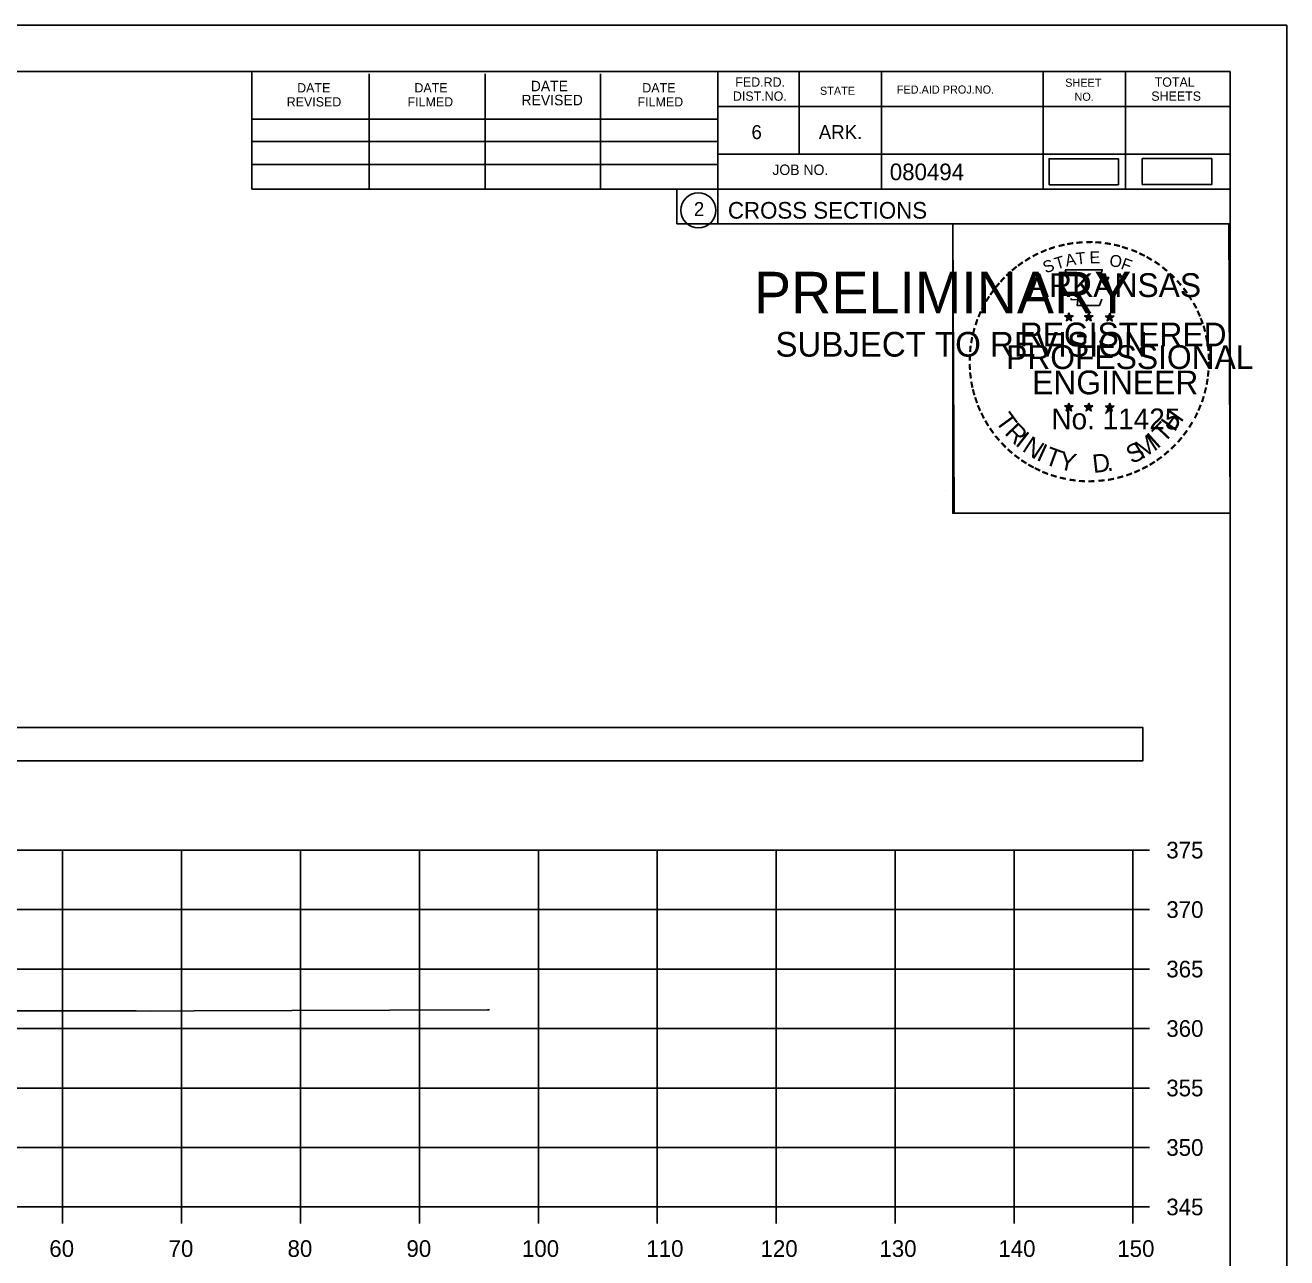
# Model space of a CAD drawing. Extents: x 1376273 to 1384221, y 378927 to 384592.
# Drawn here: x 1379448 to 1379554.1, y 381501.6 to 381605.2 of the extents above; entities that cross this region are included whole.
import ezdxf

# ---------------------------------------------------------------- set-up
doc = ezdxf.new("R2010")
doc.units = 0
for name, color, linetype in [('R_Axis', 7, 'Continuous'), ('R_Axis Annot', 7, 'Continuous'), ('R_Border', 7, 'Continuous'), ('R_Border PE', 7, 'Continuous'), ('R_Border Prem', 7, 'Continuous'), ('R_Drive', 7, 'Continuous'), ('R_Exist Surface', 7, 'Continuous'), ('R_Grid', 7, 'Continuous'), ('R_No Plot', 7, 'Continuous')]:
    doc.layers.add(name, color=color, linetype=linetype)

msp = doc.modelspace()

# ---------------------------------------------------------------- linework, layer by layer
at = {"layer": 'R_Axis'}
for p, q in [((1379541.15, 381505.85), (1379541.15, 381535.85)), ((1379542.55, 381535.85), (1379541.15, 381535.85)), ((1379542.55, 381530.85), (1379541.15, 381530.85)), ((1379542.55, 381525.85), (1379541.15, 381525.85)), ((1379542.55, 381520.85), (1379541.15, 381520.85)), ((1379542.55, 381515.85), (1379541.15, 381515.85)), ((1379542.55, 381510.85), (1379541.15, 381510.85)), ((1379241.15, 381505.85), (1379541.15, 381505.85)), ((1379451.15, 381504.45), (1379451.15, 381505.85)), ((1379461.15, 381504.45), (1379461.15, 381505.85)), ((1379471.15, 381504.45), (1379471.15, 381505.85)), ((1379481.15, 381504.45), (1379481.15, 381505.85)), ((1379491.15, 381504.45), (1379491.15, 381505.85)), ((1379501.15, 381504.45), (1379501.15, 381505.85)), ((1379511.15, 381504.45), (1379511.15, 381505.85)), ((1379521.15, 381504.45), (1379521.15, 381505.85)), ((1379531.15, 381504.45), (1379531.15, 381505.85)), ((1379541.15, 381504.45), (1379541.15, 381505.85)), ((1379542.55, 381505.85), (1379541.15, 381505.85))]:
    msp.add_line(p, q, dxfattribs=at)
at = {"layer": 'R_Axis Annot'}
msp.add_lwpolyline([(1379240.17, 381543.35), (1379541.97, 381543.35), (1379541.97, 381546.17), (1379240.17, 381546.17)], close=True, dxfattribs=at)
at = {"layer": 'R_Border'}
for p, q in [((1379233.15, 381601.31), (1379549.33, 381601.31)), ((1379467.07, 381591.43), (1379467.07, 381601.31)), ((1379476.93, 381591.43), (1379476.93, 381601.11)), ((1379486.69, 381591.43), (1379486.69, 381601.11)), ((1379496.37, 381591.43), (1379496.37, 381601.11)), ((1379506.23, 381601.31), (1379506.23, 381588.51)), ((1379513.07, 381601.31), (1379513.07, 381594.37)), ((1379520.01, 381601.31), (1379520.01, 381591.43)), ((1379533.59, 381601.31), (1379533.59, 381591.43)), ((1379540.53, 381601.31), (1379540.53, 381591.43)), ((1379549.33, 381395.85), (1379549.33, 381601.31)), ((1379549.33, 381598.37), (1379506.23, 381598.37)), ((1379549.33, 381598.39), (1379549.33, 381598.39)), ((1379467.07, 381597.29), (1379506.23, 381597.29)), ((1379467.07, 381595.43), (1379506.23, 381595.43)), ((1379549.33, 381594.37), (1379506.23, 381594.37)), ((1379509.19, 381594.37), (1379549.33, 381594.37)), ((1379467.07, 381591.43), (1379467.07, 381593.49)), ((1379467.07, 381593.49), (1379506.23, 381593.49)), ((1379549.33, 381591.43), (1379467.07, 381591.43)), ((1379506.23, 381588.51), (1379549.33, 381588.51))]:
    msp.add_line(p, q, dxfattribs=at)
msp.add_circle((1379504.61, 381589.64), 1.47, dxfattribs=at)
at = {"layer": 'R_Border PE'}
for p, q in [((1379535.41, 381580.76), (1379535.76, 381580.65)), ((1379535.41, 381580.76), (1379535.67, 381580.72)), ((1379535.41, 381580.76), (1379535.65, 381580.64)), ((1379535.55, 381580.35), (1379535.76, 381580.65)), ((1379535.55, 381580.35), (1379535.67, 381580.6)), ((1379535.55, 381580.35), (1379535.76, 381580.57)), ((1379535.76, 381581.02), (1379535.72, 381580.76)), ((1379535.76, 381580.65), (1379535.76, 381581.02)), ((1379535.76, 381581.02), (1379535.81, 381580.77)), ((1379536.11, 381580.76), (1379535.76, 381580.65)), ((1379535.97, 381580.35), (1379535.76, 381580.65)), ((1379535.97, 381580.35), (1379535.76, 381580.57)), ((1379536.11, 381580.76), (1379535.82, 381580.71)), ((1379535.97, 381580.35), (1379535.84, 381580.64)), ((1379536.11, 381580.76), (1379535.9, 381580.66)), ((1379537.08, 381580.76), (1379537.43, 381580.65)), ((1379537.08, 381580.76), (1379537.34, 381580.72)), ((1379537.08, 381580.76), (1379537.32, 381580.64)), ((1379537.22, 381580.35), (1379537.43, 381580.65)), ((1379537.22, 381580.35), (1379537.34, 381580.6)), ((1379537.22, 381580.35), (1379537.43, 381580.57)), ((1379537.43, 381581.02), (1379537.39, 381580.76)), ((1379537.43, 381580.65), (1379537.43, 381581.02)), ((1379537.43, 381581.02), (1379537.48, 381580.77)), ((1379537.78, 381580.76), (1379537.43, 381580.65)), ((1379537.64, 381580.35), (1379537.43, 381580.65)), ((1379537.64, 381580.35), (1379537.43, 381580.57)), ((1379537.78, 381580.76), (1379537.49, 381580.71)), ((1379537.64, 381580.35), (1379537.51, 381580.64)), ((1379537.78, 381580.76), (1379537.57, 381580.66)), ((1379538.85, 381580.75), (1379539.2, 381580.64)), ((1379538.85, 381580.75), (1379539.1, 381580.7)), ((1379538.85, 381580.75), (1379539.08, 381580.63)), ((1379538.98, 381580.34), (1379539.2, 381580.64)), ((1379538.98, 381580.34), (1379539.11, 381580.59)), ((1379538.98, 381580.34), (1379539.19, 381580.56)), ((1379539.2, 381581), (1379539.15, 381580.75)), ((1379539.41, 381580.34), (1379539.19, 381580.56)), ((1379539.2, 381580.64), (1379539.2, 381581)), ((1379539.2, 381581), (1379539.24, 381580.75)), ((1379539.54, 381580.75), (1379539.2, 381580.64)), ((1379539.41, 381580.34), (1379539.2, 381580.64)), ((1379539.54, 381580.75), (1379539.26, 381580.7)), ((1379539.41, 381580.34), (1379539.27, 381580.63)), ((1379539.54, 381580.75), (1379539.34, 381580.65)), ((1379535.41, 381573.19), (1379535.76, 381573.08)), ((1379535.41, 381573.19), (1379535.66, 381573.14)), ((1379535.41, 381573.19), (1379535.65, 381573.07)), ((1379535.54, 381572.78), (1379535.76, 381573.08)), ((1379535.54, 381572.78), (1379535.67, 381573.02)), ((1379535.54, 381572.78), (1379535.76, 381573)), ((1379535.76, 381573.44), (1379535.72, 381573.19)), ((1379535.76, 381573.08), (1379535.76, 381573.44)), ((1379535.76, 381573.44), (1379535.81, 381573.19)), ((1379536.1, 381573.19), (1379535.76, 381573.08)), ((1379535.97, 381572.78), (1379535.76, 381573.08)), ((1379535.97, 381572.78), (1379535.76, 381572.99)), ((1379536.1, 381573.19), (1379535.82, 381573.14)), ((1379535.97, 381572.78), (1379535.83, 381573.07)), ((1379536.1, 381573.19), (1379535.9, 381573.09)), ((1379537.08, 381573.19), (1379537.43, 381573.08)), ((1379537.08, 381573.19), (1379537.33, 381573.14)), ((1379537.08, 381573.19), (1379537.31, 381573.07)), ((1379537.21, 381572.78), (1379537.43, 381573.08)), ((1379537.21, 381572.78), (1379537.34, 381573.02)), ((1379537.21, 381572.78), (1379537.42, 381573)), ((1379537.43, 381573.44), (1379537.39, 381573.19)), ((1379537.64, 381572.78), (1379537.42, 381572.99)), ((1379537.43, 381573.08), (1379537.43, 381573.44)), ((1379537.43, 381573.44), (1379537.48, 381573.19)), ((1379537.77, 381573.19), (1379537.43, 381573.08)), ((1379537.64, 381572.78), (1379537.43, 381573.08)), ((1379537.77, 381573.19), (1379537.49, 381573.14)), ((1379537.64, 381572.78), (1379537.5, 381573.07)), ((1379537.77, 381573.19), (1379537.57, 381573.09)), ((1379538.84, 381573.18), (1379539.19, 381573.07)), ((1379538.84, 381573.18), (1379539.1, 381573.13)), ((1379538.84, 381573.18), (1379539.08, 381573.06)), ((1379538.98, 381572.77), (1379539.19, 381573.07)), ((1379538.98, 381572.77), (1379539.1, 381573.01)), ((1379538.98, 381572.77), (1379539.19, 381572.99)), ((1379539.19, 381573.43), (1379539.15, 381573.18)), ((1379539.19, 381573.07), (1379539.19, 381573.43)), ((1379539.19, 381573.43), (1379539.24, 381573.18)), ((1379539.54, 381573.18), (1379539.19, 381573.07)), ((1379539.41, 381572.77), (1379539.19, 381573.07)), ((1379539.41, 381572.77), (1379539.19, 381572.98)), ((1379539.54, 381573.18), (1379539.25, 381573.13)), ((1379539.41, 381572.77), (1379539.27, 381573.06)), ((1379539.54, 381573.18), (1379539.34, 381573.08))]:
    msp.add_line(p, q, dxfattribs=at)
for points in [[(1379535.45, 381584.64), (1379535.72, 381583.81)], [(1379538.96, 381583.72), (1379539.11, 381584), (1379538.42, 381583.98), (1379538.57, 381584.64), (1379535.45, 381584.64)], [(1379535.95, 381582.22), (1379535.95, 381582.13), (1379536.51, 381582.11), (1379536.45, 381581.64), (1379538.32, 381581.64), (1379538.53, 381582.17)], [(1379535.76, 381581.02), (1379535.97, 381580.35), (1379535.41, 381580.76), (1379536.11, 381580.76), (1379535.55, 381580.35), (1379535.76, 381581.02)], [(1379537.43, 381581.02), (1379537.64, 381580.35), (1379537.08, 381580.76), (1379537.78, 381580.76), (1379537.22, 381580.35), (1379537.43, 381581.02)], [(1379539.2, 381581), (1379539.41, 381580.34), (1379538.85, 381580.75), (1379539.54, 381580.75), (1379538.98, 381580.34), (1379539.2, 381581)], [(1379535.76, 381573.44), (1379535.97, 381572.78), (1379535.41, 381573.19), (1379536.1, 381573.19), (1379535.54, 381572.78), (1379535.76, 381573.44)], [(1379537.43, 381573.44), (1379537.64, 381572.78), (1379537.08, 381573.19), (1379537.77, 381573.19), (1379537.21, 381572.78), (1379537.43, 381573.44)], [(1379539.19, 381573.43), (1379539.41, 381572.77), (1379538.84, 381573.18), (1379539.54, 381573.18), (1379538.98, 381572.77), (1379539.19, 381573.43)]]:
    msp.add_lwpolyline(points, dxfattribs=at)
for centre, radius in [((1379535.76, 381580.65), 0.172), ((1379535.76, 381580.65), 0.145), ((1379535.76, 381580.65), 0.116), ((1379535.76, 381580.65), 0.0991), ((1379535.76, 381580.65), 0.0747), ((1379535.76, 381580.65), 0.0495), ((1379535.76, 381580.65), 0.0296), ((1379537.43, 381580.65), 0.172), ((1379537.43, 381580.65), 0.145), ((1379537.43, 381580.65), 0.116), ((1379537.43, 381580.65), 0.0991), ((1379537.43, 381580.65), 0.0747), ((1379537.43, 381580.65), 0.0495), ((1379537.43, 381580.65), 0.0296), ((1379539.19, 381580.64), 0.172), ((1379539.19, 381580.64), 0.145), ((1379539.19, 381580.64), 0.116), ((1379539.19, 381580.64), 0.0991), ((1379539.19, 381580.64), 0.0747), ((1379539.19, 381580.64), 0.0495), ((1379539.19, 381580.64), 0.0296), ((1379535.76, 381573.08), 0.172), ((1379535.76, 381573.08), 0.145), ((1379535.76, 381573.08), 0.116), ((1379535.76, 381573.08), 0.0991), ((1379535.76, 381573.08), 0.0747), ((1379535.76, 381573.08), 0.0495), ((1379535.76, 381573.08), 0.0296), ((1379537.43, 381573.08), 0.172), ((1379537.43, 381573.08), 0.145), ((1379537.43, 381573.08), 0.116), ((1379537.43, 381573.08), 0.0991), ((1379537.43, 381573.08), 0.0747), ((1379537.43, 381573.08), 0.0495), ((1379537.43, 381573.08), 0.0296), ((1379539.19, 381573.07), 0.172), ((1379539.19, 381573.07), 0.145), ((1379539.19, 381573.07), 0.116), ((1379539.19, 381573.07), 0.0991), ((1379539.19, 381573.07), 0.0747), ((1379539.19, 381573.07), 0.0495), ((1379539.19, 381573.07), 0.0296)]:
    msp.add_circle(centre, radius, dxfattribs=at)
at = {"layer": 'R_Drive'}
for points in [[(1379534.09, 381591.79), (1379539.92, 381591.79), (1379539.92, 381593.98), (1379534.09, 381593.98)], [(1379541.93, 381591.81), (1379547.77, 381591.81), (1379547.77, 381593.99), (1379541.93, 381593.99)]]:
    msp.add_lwpolyline(points, close=True, dxfattribs=at)
at = {"layer": 'R_Exist Surface'}
msp.add_lwpolyline([(1379441.1, 381522.35), (1379457.33, 381522.33), (1379458.52, 381522.32), (1379462.2, 381522.34), (1379486.88, 381522.43), (1379486.96, 381522.41), (1379486.99, 381522.41), (1379487.01, 381522.41), (1379487.03, 381522.4)], dxfattribs=at)
at = {"layer": 'R_Grid'}
for p, q in [((1379241.15, 381535.85), (1379541.15, 381535.85)), ((1379451.15, 381505.85), (1379451.15, 381535.85)), ((1379461.15, 381505.85), (1379461.15, 381535.85)), ((1379471.15, 381505.85), (1379471.15, 381535.85)), ((1379481.15, 381505.85), (1379481.15, 381535.85)), ((1379491.15, 381505.85), (1379491.15, 381535.85)), ((1379501.15, 381505.85), (1379501.15, 381535.85)), ((1379511.15, 381505.85), (1379511.15, 381535.85)), ((1379521.15, 381505.85), (1379521.15, 381535.85)), ((1379531.15, 381505.85), (1379531.15, 381535.85)), ((1379541.15, 381505.85), (1379541.15, 381535.85)), ((1379241.15, 381530.85), (1379541.15, 381530.85)), ((1379241.15, 381525.85), (1379541.15, 381525.85)), ((1379241.15, 381520.85), (1379541.15, 381520.85)), ((1379241.15, 381515.85), (1379541.15, 381515.85)), ((1379241.15, 381510.85), (1379541.15, 381510.85)), ((1379241.15, 381505.85), (1379541.15, 381505.85))]:
    msp.add_line(p, q, dxfattribs=at)
at = {"layer": 'R_No Plot'}
for p, q in [((1379220.75, 381605.2), (1379554.08, 381605.2)), ((1379525.36, 381566.05), (1379525.36, 381566.05))]:
    msp.add_line(p, q, dxfattribs=at)
for points in [[(1379220.74, 381605.2), (1379554.08, 381605.2), (1379554.08, 381391.86), (1379220.74, 381391.86)], [(1379467.07, 381601.31), (1379467.07, 381591.43), (1379502.8, 381591.43), (1379502.8, 381588.51), (1379526, 381588.51), (1379526, 381564.17), (1379549.33, 381564.17), (1379549.33, 381395.85), (1379233.15, 381395.85), (1379233.15, 381601.31)], [(1379526, 381588.51), (1379549.21, 381588.51), (1379549.33, 381564.17), (1379526.12, 381564.17)]]:
    msp.add_lwpolyline(points, close=True, dxfattribs=at)

# ---------------------------------------------------------------- texts
at = {"layer": 'R_Axis Annot'}
for s, p in [('375', (1379543.95, 381535.15)), ('370', (1379543.95, 381530.15)), ('365', (1379543.95, 381525.15)), ('360', (1379543.95, 381520.15)), ('355', (1379543.95, 381515.15)), ('350', (1379543.95, 381510.15)), ('345', (1379543.95, 381505.15)), ('60', (1379450.03, 381501.65)), ('70', (1379460.06, 381501.65)), ('80', (1379470.06, 381501.65)), ('90', (1379480.06, 381501.65)), ('100', (1379489.77, 381501.65)), ('110', (1379500.23, 381501.65)), ('120', (1379509.83, 381501.65)), ('130', (1379519.83, 381501.65)), ('140', (1379529.83, 381501.65)), ('150', (1379539.83, 381501.65))]:
    msp.add_text(s, height=1.4, dxfattribs=at).set_placement(p)
at = {"layer": 'R_Border'}
for s, height, p in [('DATE', 0.782, (1379470.87, 381599.55)), ('DATE', 0.782, (1379480.73, 381599.55)), ('DATE', 0.879, (1379490.51, 381599.65)), ('DATE', 0.782, (1379499.89, 381599.55)), ('FED.RD.', 0.782, (1379507.71, 381600.03)), ('SHEET', 0.684, (1379535.45, 381600.03)), ('TOTAL', 0.782, (1379542.97, 381600.03)), ('REVISED', 0.879, (1379489.73, 381598.47)), ('DIST.NO.', 0.782, (1379507.51, 381598.85)), ('STATE', 0.684, (1379514.83, 381599.35)), ('FED.AID PROJ.NO.', 0.684, (1379521.29, 381599.45)), ('NO.', 0.684, (1379536.23, 381598.85)), ('SHEETS', 0.782, (1379542.69, 381598.85)), ('REVISED', 0.782, (1379469.99, 381598.37)), ('FILMED', 0.782, (1379480.15, 381598.37)), ('FILMED', 0.782, (1379499.49, 381598.37)), ('6', 1.17, (1379509.07, 381595.63)), ('ARK.', 1.172, (1379514.73, 381595.63)), ('JOB NO.', 0.879, (1379510.83, 381592.61)), ('080494', 1.4, (1379520.7, 381592.17)), ('2', 1.17, (1379504.23, 381589.16)), ('CROSS SECTIONS', 1.4, (1379507.09, 381588.94))]:
    msp.add_text(s, height=height, rotation=360, dxfattribs=at).set_placement(p)
at = {"layer": 'R_Border PE'}
for s, height, rotation, p in [('-', 1.6, 19.1761, (1379534.2, 381585.77)), ('-', 1.6, 13.6301, (1379534.95, 381586.01)), ('-', 1.6, 10.2193, (1379535.63, 381586.17)), ('-', 1.6, 5.8968, (1379536.36, 381586.28)), ('-', 1.6, 0.1862, (1379537.13, 381586.35)), ('-', 1.6, 357.743, (1379537.85, 381586.34)), ('-', 1.6, 352.1617, (1379538.6, 381586.28)), ('-', 1.6, 347.2049, (1379539.32, 381586.17)), ('-', 1.6, 342.3362, (1379539.95, 381586.01)), ('-', 1.6, 34.0636, (1379532.34, 381584.81)), ('-', 1.6, 28.7918, (1379532.93, 381585.18)), ('-', 1.6, 24.3072, (1379533.57, 381585.5)), ('S', 1, 21.594, (1379533.81, 381584.32)), ('T', 1, 16.4036, (1379534.72, 381584.65)), ('A', 1, 11.2132, (1379535.55, 381584.9)), ('T', 1, 6.0228, (1379536.4, 381585.07)), ('E', 1, 0.8323, (1379537.5, 381585.18)), ('O', 1, 350.4515, (1379539.11, 381584.97)), ('F', 1, 340.0707, (1379540.06, 381584.74)), ('-', 1.6, 337.8551, (1379540.69, 381585.79)), ('-', 1.6, 334.1211, (1379541.32, 381585.52)), ('-', 1.6, 329.6409, (1379541.9, 381585.24)), ('-', 1.6, 325.8627, (1379542.54, 381584.88)), ('-', 1.6, 42.9622, (1379530.85, 381583.62)), ('-', 1.6, 38.9507, (1379531.28, 381584.04)), ('-', 1.6, 36.2317, (1379531.76, 381584.42)), ('ARKANSAS', 2, 360, (1379532.31, 381582.35)), ('-', 1.6, 320.5297, (1379543.15, 381584.45)), ('-', 1.6, 315.5786, (1379543.75, 381583.96)), ('-', 1.6, 50.6142, (1379530, 381582.66)), ('-', 1.6, 48.423, (1379530.4, 381583.14)), ('-', 1.6, 309.8797, (1379544.32, 381583.41)), ('-', 1.6, 58.0706, (1379529.26, 381581.56)), ('-', 1.6, 54.2325, (1379529.59, 381582.09)), ('-', 1.6, 306.6522, (1379544.84, 381582.81)), ('-', 1.4, 303.6753, (1379545.33, 381582.24)), ('-', 1.6, 67.7743, (1379528.69, 381580.34)), ('-', 1.6, 62.8713, (1379528.95, 381580.95)), ('-', 1.6, 299.6684, (1379545.65, 381581.63)), ('-', 1.6, 294.6628, (1379545.97, 381581.02)), ('-', 1.6, 72.3945, (1379528.47, 381579.71)), ('REGISTERED', 2, 360, (1379531.63, 381578.2)), ('DWB', 0.01, 360, (1379535.75, 381580.65)), ('DWB', 0.01, 360, (1379537.42, 381580.65)), ('DWB', 0.01, 360, (1379539.18, 381580.63)), ('-', 1.6, 290.5728, (1379546.23, 381580.45)), ('-', 1.6, 75.461, (1379528.27, 381578.99)), ('-', 1.6, 285.1233, (1379546.46, 381579.87)), ('-', 1.6, 280.5493, (1379546.66, 381579.12)), ('-', 1.6, 85.1863, (1379528.06, 381577.59)), ('-', 1.6, 81.2013, (1379528.14, 381578.28)), ('PROFESSIONAL', 2, 360, (1379530.48, 381576.3)), ('-', 1.6, 276.5962, (1379546.82, 381578.36)), ('-', 1.6, 89.0622, (1379528.04, 381576.89)), ('-', 1.6, 274.3301, (1379546.88, 381577.63)), ('-', 1.6, 94.1959, (1379528.07, 381576.16)), ('-', 1.6, 98.9479, (1379528.15, 381575.5)), ('ENGINEER', 2, 360, (1379532.67, 381574.17)), ('-', 1.6, 263.5172, (1379546.9, 381576.34)), ('-', 1.6, 269.9407, (1379546.92, 381577)), ('-', 1.6, 101.7149, (1379528.28, 381574.76)), ('-', 1.6, 260.9953, (1379546.83, 381575.68)), ('-', 1.6, 105.4578, (1379528.44, 381574.17)), ('-', 1.6, 109.0874, (1379528.66, 381573.54)), ('-', 1.6, 252.8681, (1379546.54, 381574.28)), ('-', 1.6, 255.7626, (1379546.72, 381575)), ('-', 1.6, 114.0643, (1379528.91, 381572.94)), ('T', 1.54, 306.0406, (1379529.52, 381571.92)), ('No. 11425', 1.757, 360, (1379534.29, 381571.22)), ('DWB', 0.01, 360, (1379535.74, 381573.07)), ('DWB', 0.01, 360, (1379537.41, 381573.07)), ('DWB', 0.01, 360, (1379539.18, 381573.06)), ('H', 1.54, 54.6088, (1379544.64, 381570.95)), ('-', 1.6, 247.8887, (1379546.31, 381573.61)), ('-', 1.6, 115.7289, (1379529.22, 381572.32)), ('-', 1.6, 120.4471, (1379529.57, 381571.74)), ('R', 1.54, 314.005, (1379530.28, 381570.87)), ('T', 1.54, 46.6444, (1379543.75, 381570.01)), ('-', 1.6, 239.0712, (1379545.66, 381572.23)), ('-', 1.6, 244.6197, (1379546.05, 381572.98)), ('-', 1.6, 125.8934, (1379529.98, 381571.18)), ('-', 1.6, 130.7181, (1379530.44, 381570.62)), ('I', 1.54, 321.9694, (1379531.18, 381569.94)), ('N', 1.54, 326.5002, (1379531.75, 381569.46)), ('M', 1.54, 32.6563, (1379541.9, 381568.68)), ('I', 1.54, 42.1136, (1379543.19, 381569.53)), ('-', 1.6, 231.2538, (1379544.83, 381571.01)), ('-', 1.6, 233.8452, (1379545.26, 381571.58)), ('-', 1.6, 134.2238, (1379530.96, 381570.08)), ('-', 1.6, 138.9338, (1379531.48, 381569.62)), ('I', 1.54, 335.3603, (1379532.95, 381568.68)), ('T', 1.54, 339.8912, (1379533.62, 381568.35)), ('S', 1.54, 26.9312, (1379541.06, 381568.28)), ('-', 1.6, 225.7653, (1379544.35, 381570.45)), ('-', 1.6, 144.6463, (1379532.04, 381569.21)), ('-', 1.6, 148.0898, (1379532.6, 381568.84)), ('Y', 1.54, 347.8556, (1379534.83, 381567.91)), ('D', 1.54, 6.3969, (1379537.82, 381567.55)), ('-', 1.6, 212.2491, (1379542.74, 381569.08)), ('-', 1.6, 215.7363, (1379543.28, 381569.47)), ('-', 1.6, 221.0851, (1379543.82, 381569.94)), ('-', 1.6, 151.5704, (1379533.18, 381568.51)), ('-', 1.6, 154.6002, (1379533.7, 381568.27)), ('-', 1.6, 158.5612, (1379534.32, 381568.01)), ('-', 1.6, 162.7983, (1379535.01, 381567.8)), ('.', 1.54, 13.7642, (1379539.01, 381567.67)), ('-', 1.6, 200.7184, (1379540.94, 381568.14)), ('-', 1.6, 204.2516, (1379541.56, 381568.41)), ('-', 1.6, 207.3568, (1379542.18, 381568.73)), ('-', 1.6, 167.5555, (1379535.73, 381567.64)), ('-', 1.6, 173.1155, (1379536.5, 381567.53)), ('-', 1.6, 176.5183, (1379537.25, 381567.47)), ('-', 1.6, 181.5918, (1379537.99, 381567.49)), ('-', 1.6, 185.8167, (1379538.8, 381567.57)), ('-', 1.6, 191.2858, (1379539.53, 381567.7)), ('-', 1.6, 195.4743, (1379540.26, 381567.9))]:
    msp.add_text(s, height=height, rotation=rotation, dxfattribs=at).set_placement(p)
at = {"layer": 'R_Border Prem'}
for s, height, p in [('PRELIMINARY', 3.5, (1379509.28, 381580.97)), ('DWB', 0.01, (1379510.02, 381582.82)), ('SUBJECT TO REVISION', 2.0751, (1379511.09, 381577.34))]:
    msp.add_text(s, height=height, rotation=360, dxfattribs=at).set_placement(p)

doc.saveas('drawing.dxf')
